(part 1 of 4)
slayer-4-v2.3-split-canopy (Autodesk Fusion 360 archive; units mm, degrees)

design "slayer-4-v2.3" references "20x20 Flight Controller", "M3 x 0.5mm Thread 6mm LONG SOCKET HEAD CAP SCREW", "runcam_phoenix_2", "CADDXFPV Ratel 2.1mm", "Slayer Hurricane 4040", "EACHINE CCW TYRO79-1607-2800KV", "M2 x 0.4mm Thread 5mm LONG SOCKET HEAD CAP SCREW"
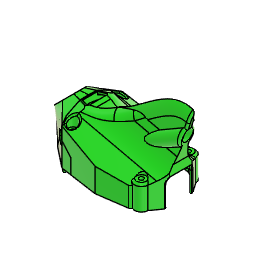
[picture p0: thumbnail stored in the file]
parameter "armstrength" = 5
parameter "d11" = 33
parameter "d12" = 48
parameter "d547" = 2
sketch "center-upper" plane through (0, 0, 0) normal (0, 0, 1) x axis (1, 0, 0)
  line L1 (-93, 0) -> (0, 0)
  line L2 (0, 100) -> (0, 0)
  line L3 (-24, 16.5) -> (-18.1019, 0)
  line L4 (0, 18.1019) -> (-24, 16.5)
  line L5 (0, 18.1019) -> (-10, 10)
  line L6 (-10, 10) -> (-18.1019, 0)
  line L7 (-25.4125, 15.9951) -> (-19.6949, 0)
  line L8 (-22.5875, 17.0049) -> (-16.509, 0)
  line L9 (-11.1655, 10.9443) -> (-20.0325, 0)
  line L10 (-8.8345, 9.0557) -> (-16.1714, 0)
  line L11 (-10.9443, 11.1655) -> (-0.9443, 19.2674)
  line L12 (-9.0557, 8.8345) -> (0.9443, 16.9364)
  line L13 (-35, 0) -> (0, 0)
  line L14 (-22.5875, 17.0049) -> (-24, 16.5)
  line L15 (-25.4125, 15.9951) -> (-24, 16.5)
  line L16 (-11.1655, 10.9443) -> (-10, 10)
  line L17 (-8.8345, 9.0557) -> (-10, 10)
  line L18 (-10.9443, 11.1655) -> (-10, 10)
  line L19 (-9.0557, 8.8345) -> (-10, 10)
  line L20 (-0.9443, 19.2674) -> (0, 18.1019)
  line L21 (0.9443, 16.9364) -> (0, 18.1019)
  line L22 (0.0999, 16.6053) -> (-23.9001, 15.0033)
  line L23 (-0.0999, 19.5986) -> (-24.0999, 17.9967)
  line L24 (-24.0999, 17.9967) -> (-24, 16.5)
  line L25 (-23.9001, 15.0033) -> (-24, 16.5)
  line L26 (-0.0999, 19.5986) -> (0, 18.1019)
  line L27 (0.0999, 16.6053) -> (0, 18.1019)
  line L28 (0, 30) -> (0, 0)
  line L29 (0, 1.5) -> (-18.1019, 1.5)
  line L30 (-18.1019, 1.5) -> (-18.1019, 0)
  line L31 (0, 0) -> (-10, 10)
  line L32 (-14.1459, 2.5) -> (0, 2.5)
  line L33 (-7.5042, 2.5) -> (-10, 10)
  circle C1 centre (-24, 16.5) radius 1.55
  circle C2 centre (0, 18.1019) radius 1.05
  circle C3 centre (-18.1019, 0) radius 1.05
  circle C4 centre (-10, 10) radius 1.05
  circle C5 centre (-24, 16.5) radius 5.5
  circle C6 centre (0, 18.1019) radius 3
  circle C7 centre (-10, 10) radius 3
  circle C8 centre (-18.1019, 0) radius 3
  point P3 (-24, 16.5)
  point P5 (-24, 16.5)
  point P1 (0, 0)
  point P6 (0, 0)
  point P4 (-18.1019, 0)
  point P8 (0, 0)
  point P2 (0, 18.1019)
  point P11 (-18.1019, 0)
  point P12 (-24, 16.5)
  point P13 (0, 18.1019)
  point P10 (-10, 10)
  point P14 (-10, 10)
  point P20 (-20.0325, 0)
  point P22 (-16.1714, 0)
  point P31 (0, 0)
  point P32 (-35, 0)
  point P33 (-24, 16.5)
  point P34 (-22.5875, 17.0049)
  point P19 (-24, 16.5)
  point P35 (-24, 16.5)
  point P36 (-25.4125, 15.9951)
  point P18 (-22.5875, 17.0049)
  point P16 (-25.4125, 15.9951)
  point P17 (-16.509, 0)
  point P15 (-19.6949, 0)
  point P29 (-10, 10)
  point P37 (-10, 10)
  point P38 (-11.1655, 10.9443)
  point P39 (-10, 10)
  point P40 (-8.8345, 9.0557)
  point P41 (-10, 10)
  point P42 (-10.9443, 11.1655)
  point P43 (-9.0557, 8.8345)
  point P25 (-10.9443, 11.1655)
  point P21 (-11.1655, 10.9443)
  point P23 (-8.8345, 9.0557)
  point P27 (-9.0557, 8.8345)
  point P44 (0, 18.1019)
  point P45 (-0.9443, 19.2674)
  point P46 (0.9443, 16.9364)
  point P24 (-0.9443, 19.2674)
  point P26 (0.9443, 16.9364)
  point P51 (-24.0999, 17.9967)
  point P52 (-24, 16.5)
  point P53 (-23.9001, 15.0033)
  point P49 (-24.0999, 17.9967)
  point P47 (-23.9001, 15.0033)
  point P28 (0, 18.1019)
  point P54 (0, 18.1019)
  point P55 (-0.0999, 19.5986)
  point P56 (0.0999, 16.6053)
  point P50 (-0.0999, 19.5986)
  point P48 (0.0999, 16.6053)
  point P57 (0, 30)
  point P60 (-18.1019, 0)
  point P61 (0, 2.5)
  point P62 (-14.1459, 2.5)
  point P63 (-7.5042, 2.5)
  coincident P3 P5
  coincident P1 P6
  coincident P4 L1
  coincident P1 P8
  coincident P2 L2
  coincident P4 P11
  coincident P3 P12
  coincident P2 P13
  coincident P10 P14
  parallel L3 L7
  parallel L3 L8
  concentric C1 C5
  coincident L1 P20
  parallel L6 L9
  coincident L1 P22
  parallel L6 L10
  parallel L5 L11
  parallel L5 L12
  concentric C2 C6
  concentric C4 C7
  concentric C3 C8
  coincident P1 P31
  coincident L1 P32
  perpendicular L2 L13
  coincident P3 P33
  coincident L8 P34
  perpendicular L8 L14
  coincident P19 P35
  coincident L7 P36
  perpendicular L7 L15
  coincident P18 P34
  coincident P16 P36
  coincident L1 P17
  coincident P15 L13
  coincident P29 P37
  coincident L9 P38
  perpendicular L9 L16
  coincident P10 P39
  coincident L10 P40
  perpendicular L10 L17
  coincident P29 P41
  coincident L11 P42
  perpendicular L11 L18
  coincident L12 P43
  perpendicular L12 L19
  coincident P25 L19
  coincident P21 P38
  coincident P23 P40
  coincident P27 P43
  coincident P2 P44
  coincident L11 P45
  perpendicular L11 L20
  coincident L12 P46
  perpendicular L12 L21
  coincident P24 P45
  coincident P26 P46
  parallel L4 L22
  parallel L4 L23
  coincident L23 P51
  perpendicular L23 L24
  coincident P3 P52
  coincident L22 P53
  perpendicular L22 L25
  coincident P49 P51
  coincident P47 P53
  coincident P28 P54
  coincident L23 P55
  perpendicular L23 L26
  coincident L22 P56
  perpendicular L22 L27
  coincident P50 P55
  coincident P48 P56
  coincident L2 P57
  horizontal L29
  coincident P4 P60
  perpendicular L29 L30
  coincident L28 P61
  coincident L10 P62
  perpendicular L28 L32
  coincident L32 P63
  dimension "d15" distance P2 P4 = 25.6
  dimension "d17" diameter C1 = 3.1
  dimension "d21" diameter C2 = 2.1
  dimension "d24" diameter C3 = 2.1 (= "d21")
  dimension "d27" distance P3 L1 = 16.5 (= "d11 / 2")
  dimension "d28" distance P3 L2 = 24 (= "d12 / 2")
  dimension "d34" diameter C4 = 2.1 (= "d21")
  dimension "d38" distance L2 P10 = 10
  dimension "d39" distance L1 P10 = 10
  dimension "d44" distance L3 L7 = 1.5
  dimension "d45" distance L3 L8 = 1.5 (= "d44")
  dimension "d47" distance L6 L9 = 1.5 (= "d44")
  dimension "d48" distance L6 L10 = 1.5 (= "d44")
  dimension "d49" distance L5 L11 = 1.5 (= "d44")
  dimension "d50" distance L5 L12 = 1.5 (= "d44")
  dimension "d51" diameter C5 = 11
  dimension "d52" diameter C8 = 6
  dimension "d53" diameter C7 = 6
  dimension "d54" diameter C6 = 6
  dimension "d55" distance L4 L23 = 1.5 (= "d44")
  dimension "d56" distance L4 L22 = 1.5 (= "d44")
  dimension "d93" distance L1 L29 = 1.5
  dimension "d118" distance L13 L32 = 2.5
extrude "Extrude2" new body sketch "center-upper" profile of C1 C2 C3 C4 L7 L8 C5 L9 L10 L11 L12 C6 C7 C8 L13 L22 L23 L28 along normal blind 2
fillet "Fillet6" radius 2
fillet "Fillet9" radius 5
fillet "Fillet7" radius 18
fillet "Fillet10" radius 20
fillet "Fillet147" radius 5
mirror "Mirror1" mirrorStitchTolerance 0.1
mirror "Mirror2" mirrorStitchTolerance 0.1
fillet "Fillet8" radius 9
sketch "center-upper-rear-cage" plane through (0, 0, 0) normal (0, 0, -1) x axis (1, 0, 0)
  line L1 (-10.419, 18.9098) -> (-7.8768, 19.0795)
  line L2 (-7.8768, -19.0795) -> (-10.419, -18.9098)
  line L3 (10.419, -18.9098) -> (7.8768, -19.0795)
  line L4 (7.8768, 19.0795) -> (10.419, 18.9098)
  line L5 (19.6919, -8.9044) -> (18.7852, -6.3678)
  line L6 (13.4936, -15.6979) -> (15.3167, -15.5763)
  line L7 (15.3479, -5.782) -> (13.4133, -8.1699)
  line L8 (18.7852, 6.3678) -> (19.6919, 8.9044)
  line L9 (13.4133, 8.1699) -> (15.3479, 5.782)
  line L10 (15.3167, 15.5763) -> (13.4936, 15.6979)
  line L11 (-19.6919, 8.9044) -> (-18.7852, 6.3678)
  line L12 (-13.4936, 15.6979) -> (-15.3167, 15.5763)
  line L13 (-15.3479, 5.782) -> (-13.4133, 8.1699)
  line L14 (-18.7852, -6.3678) -> (-19.6919, -8.9044)
  line L15 (-13.4133, -8.1699) -> (-15.3479, -5.782)
  line L16 (-15.3167, -15.5763) -> (-13.4936, -15.6979)
  line L17 (19, 3) -> (32.4985, 3)
  line L18 (31.3257, 6) -> (20, 6)
  line L19 (35.4985, 3.9489) -> (29.0384, 18.7057)
  line L20 (35.4985, 0) -> (35.4985, 3.9489)
  line L21 (28.2548, 13.0148) -> (31.3257, 6)
  line L22 (32.4985, 0) -> (32.4985, 3)
  line L23 (35.4985, 0) -> (32.4985, 0)
  line L24 (20, 6) -> (19, 3)
  line L25 (29.0384, 18.7057) -> (28.2548, 13.0148)
  line L26 (-22.1379, 6.8345) -> (-22.6368, 8.2301)
  line L27 (-22.6368, -8.2301) -> (-22.1379, -6.8345)
  line L28 (22.1379, -6.8345) -> (22.6368, -8.2301)
  line L29 (22.6368, 8.2301) -> (22.1379, 6.8345)
  circle C1 centre (0, 18.1019) radius 1.05
  arc A1 centre (0, 18.1019) radius 3 clockwise from (-1.2965, 20.8073) to (1.2965, 20.8073)
  arc A2 centre (-9.0756, 37.0396) radius 18 clockwise from (-1.2965, 20.8073) to (-7.8768, 19.0795)
  arc A3 centre (-11.751, 38.8654) radius 20 clockwise from (-10.419, 18.9098) to (-21.3581, 21.3239)
  arc A4 centre (-24, 16.5) radius 5.5 clockwise from (-25.7522, 11.2866) to (-21.3581, 21.3239)
  arc A5 centre (-24, -16.5) radius 5.5 clockwise from (-21.3581, -21.3239) to (-25.7522, -11.2866)
  arc A6 centre (-11.751, -38.8654) radius 20 clockwise from (-21.3581, -21.3239) to (-10.419, -18.9098)
  arc A7 centre (-9.0756, -37.0396) radius 18 clockwise from (-7.8768, -19.0795) to (-1.2965, -20.8073)
  arc A8 centre (0, -18.1019) radius 3 clockwise from (1.2965, -20.8073) to (-1.2965, -20.8073)
  arc A9 centre (9.0756, -37.0396) radius 18 clockwise from (1.2965, -20.8073) to (7.8768, -19.0795)
  arc A10 centre (11.751, -38.8654) radius 20 clockwise from (10.419, -18.9098) to (21.3581, -21.3239)
  arc A11 centre (24, -16.5) radius 5.5 clockwise from (25.7522, -11.2866) to (21.3581, -21.3239)
  arc A12 centre (24, 16.5) radius 5.5 clockwise from (21.3581, 21.3239) to (25.7522, 11.2866)
  arc A13 centre (11.751, 38.8654) radius 20 clockwise from (21.3581, 21.3239) to (10.419, 18.9098)
  arc A14 centre (9.0756, 37.0396) radius 18 clockwise from (7.8768, 19.0795) to (1.2965, 20.8073)
  arc A15 centre (10, 10) radius 3 clockwise from (8.3417, 7.5) to (7.5, 8.3417)
  arc A16 centre (3.3668, 0) radius 9 clockwise from (8.3417, 7.5) to (8.3417, -7.5)
  arc A17 centre (10, -10) radius 3 clockwise from (7.5, -8.3417) to (8.3417, -7.5)
  arc A18 centre (0, -3.3668) radius 9 clockwise from (7.5, -8.3417) to (-7.5, -8.3417)
  arc A19 centre (-10, -10) radius 3 clockwise from (-8.3417, -7.5) to (-7.5, -8.3417)
  arc A20 centre (-3.3668, 0) radius 9 clockwise from (-8.3417, -7.5) to (-8.3417, 7.5)
  arc A21 centre (-10, 10) radius 3 clockwise from (-7.5, 8.3417) to (-8.3417, 7.5)
  arc A22 centre (0, 3.3668) radius 9 clockwise from (-7.5, 8.3417) to (7.5, 8.3417)
  circle C2 centre (24, -16.5) radius 1.55
  circle C3 centre (10, -10) radius 1.05
  arc A23 centre (14.9837, -10.5874) radius 5 clockwise from (19.6919, -8.9044) to (15.3167, -15.5763)
  arc A24 centre (13.3604, -13.7024) radius 2 clockwise from (13.4936, -15.6979) to (12.0163, -12.2214)
  arc A25 centre (10, -10) radius 3 clockwise from (12.9804, -9.6573) to (12.0163, -12.2214)
  arc A26 centre (14.9673, -9.4289) radius 2 clockwise from (12.9804, -9.6573) to (13.4133, -8.1699)
  arc A27 centre (16.9019, -7.041) radius 2 clockwise from (15.3479, -5.782) to (18.7852, -6.3678)
  arc A28 centre (16.9019, 7.041) radius 2 clockwise from (18.7852, 6.3678) to (15.3479, 5.782)
  arc A29 centre (14.9673, 9.4289) radius 2 clockwise from (13.4133, 8.1699) to (12.9804, 9.6573)
  arc A30 centre (10, 10) radius 3 clockwise from (12.0163, 12.2214) to (12.9804, 9.6573)
  arc A31 centre (13.3604, 13.7024) radius 2 clockwise from (12.0163, 12.2214) to (13.4936, 15.6979)
  arc A32 centre (14.9837, 10.5874) radius 5 clockwise from (15.3167, 15.5763) to (19.6919, 8.9044)
  circle C4 centre (10, 10) radius 1.05
  circle C5 centre (24, 16.5) radius 1.55
  circle C6 centre (18.1019, 0) radius 1.05
  circle C7 centre (-18.1019, 0) radius 1.05
  circle C8 centre (-24, 16.5) radius 1.55
  circle C9 centre (-10, 10) radius 1.05
  arc A33 centre (-14.9837, 10.5874) radius 5 clockwise from (-19.6919, 8.9044) to (-15.3167, 15.5763)
  arc A34 centre (-13.3604, 13.7024) radius 2 clockwise from (-13.4936, 15.6979) to (-12.0163, 12.2214)
  arc A35 centre (-10, 10) radius 3 clockwise from (-12.9804, 9.6573) to (-12.0163, 12.2214)
  arc A36 centre (-14.9673, 9.4289) radius 2 clockwise from (-12.9804, 9.6573) to (-13.4133, 8.1699)
  arc A37 centre (-16.9019, 7.041) radius 2 clockwise from (-15.3479, 5.782) to (-18.7852, 6.3678)
  arc A38 centre (-16.9019, -7.041) radius 2 clockwise from (-18.7852, -6.3678) to (-15.3479, -5.782)
  arc A39 centre (-14.9673, -9.4289) radius 2 clockwise from (-13.4133, -8.1699) to (-12.9804, -9.6573)
  arc A40 centre (-10, -10) radius 3 clockwise from (-12.0163, -12.2214) to (-12.9804, -9.6573)
  arc A41 centre (-13.3604, -13.7024) radius 2 clockwise from (-12.0163, -12.2214) to (-13.4936, -15.6979)
  arc A42 centre (-14.9837, -10.5874) radius 5 clockwise from (-15.3167, -15.5763) to (-19.6919, -8.9044)
  circle C10 centre (-10, -10) radius 1.05
  circle C11 centre (-24, -16.5) radius 1.55
  circle C12 centre (0, -18.1019) radius 1.05
  arc A43 centre (-39.0876, 0.7757) radius 18 clockwise from (-22.1379, 6.8345) to (-21.0999, 0.1108)
  arc A44 centre (-18.1019, 0) radius 3 clockwise from (-21.0999, -0.1108) to (-21.0999, 0.1108)
  arc A45 centre (-39.0876, -0.7757) radius 18 clockwise from (-21.0999, -0.1108) to (-22.1379, -6.8345)
  arc A46 centre (39.0876, -0.7757) radius 18 clockwise from (22.1379, -6.8345) to (21.0999, -0.1108)
  arc A47 centre (18.1019, 0) radius 3 clockwise from (21.0999, 0.1108) to (21.0999, -0.1108)
  arc A48 centre (39.0876, 0.7757) radius 18 clockwise from (21.0999, 0.1108) to (22.1379, 6.8345)
  arc A49 centre (-27.345, 6.5471) radius 5 clockwise from (-25.7522, 11.2866) to (-22.6368, 8.2301)
  arc A50 centre (-27.345, -6.5471) radius 5 clockwise from (-22.6368, -8.2301) to (-25.7522, -11.2866)
  arc A51 centre (27.345, -6.5471) radius 5 clockwise from (25.7522, -11.2866) to (22.6368, -8.2301)
  arc A52 centre (27.345, 6.5471) radius 5 clockwise from (22.6368, 8.2301) to (25.7522, 11.2866)
  point P114 (29.0384, 18.7057)
  point P117 (28.2548, 13.0148)
  horizontal L17
  horizontal L18
  midpoint A12 P114
  tangent A12 L19
  vertical L20
  coincident A12 P117
  parallel L19 L21
  perpendicular L17 L22
  perpendicular L20 L23
  dimension "d83" distance L17 L18 = 3
  dimension "d84" distance L19 L21 = 3
  dimension "d85" distance L20 L22 = 3
  dimension "d88" distance L17 L23 = 3
extrude "Extrude3" new body sketch "center-upper-rear-cage" profile of A12 L17 L18 L19 L20 L21 L22 L23 against normal blind 2 bodies "center-upper"
mirror "Mirror3" mirrorStitchTolerance 0.1
combine "Combine1"
fillet "Fillet11" radius 2
extrude "Extrude4" new body sketch "center-upper" profile of C3 C4 L7 L8 L9 L10 L12 C7 C8 L13 L28 L29 L30 L32 L33 no distance stored bodies "puzzle"
sketch "puzzle" plane through (0, 0, -5) normal (0, 0, -1) x axis (1, 0, 0)
  line L1 (0, 0) -> (0, -2.5)
  line L2 (-17.0519, 0) -> (0, 0)
  line L3 (-21.1019, 0) -> (-19.1519, 0)
  line L4 (-12.801, -8.9256) -> (-17.6319, -2.9629)
  line L5 (-7.5042, -2.5) -> (-9.0528, -7.1535)
  line L6 (0, -2.5) -> (-7.5042, -2.5)
  line L7 (-21.1019, -13) -> (-10, -13)
  line L8 (-21.1019, 0) -> (-21.1019, -13)
  line L9 (-15.0963, -6.0926) -> (-24, -16.5)
  line L10 (-5.2336, -20.4063) -> (-29.0797, -0.0054)
  circle C1 centre (-10, -10) radius 1.05
  arc A1 centre (-18.1019, 0) radius 1.05 clockwise from (-17.0519, 0) to (-19.1519, 0)
  arc A2 centre (-18.1019, 0) radius 3 clockwise from (-17.6319, -2.9629) to (-21.1019, 0)
  arc A3 centre (-10, -10) radius 3 clockwise from (-9.0528, -7.1535) to (-12.801, -8.9256)
  arc A4 centre (-7.8796, 0) radius 13.2223 clockwise from (-10.6223, -12.9348) to (-21.1019, 0)
  point P14 (-10.6223, -12.9348)
  point P8 (-21.1019, 0)
  point P13 (-21.1019, 0)
  point P16 (-10, -13)
  tangent A2 A4
  coincident A3 P14
  coincident P8 P13
  tangent A3 A4
  coincident A3 P16
  tangent A3 L7
  parallel L3 L7
  tangent A2 L8
  perpendicular L9 L10
extrude "Extrude6" add sketch "puzzle" profile of A2 L4 A3 A4 L7 L8 L10 no distance stored
fillet "Fillet13" radius 2
sketch "arm" plane through (0, 0, 0) normal (0, 0, -1) x axis (1, 0, 0)
  line L1 (30.099, 8.8021) -> (29.2912, 10.6474)
  line L2 (-18.7852, -6.3678) -> (-19.6919, -8.9044)
  line L3 (-13.4133, -8.1699) -> (-15.3479, -5.782)
  line L4 (-15.3167, -15.5763) -> (-13.4936, -15.6979)
  line L5 (-19.6919, 8.9044) -> (-18.7852, 6.3678)
  line L6 (-13.4936, 15.6979) -> (-15.3167, 15.5763)
  line L7 (-15.3479, 5.782) -> (-13.4133, 8.1699)
  line L8 (18.7852, 6.3678) -> (19.6919, 8.9044)
  line L9 (13.4133, 8.1699) -> (15.3479, 5.782)
  line L10 (15.3167, 15.5763) -> (13.4936, 15.6979)
  line L11 (19.6919, -8.9044) -> (18.7852, -6.3678)
  line L12 (13.4936, -15.6979) -> (15.3167, -15.5763)
  line L13 (15.3479, -5.782) -> (13.4133, -8.1699)
  line L14 (29.0384, 18.7057) -> (35.3306, 4.3323)
  line L15 (7.8768, 19.0795) -> (10.419, 18.9098)
  line L16 (-10.419, 18.9098) -> (-7.8768, 19.0795)
  line L17 (-7.8768, -19.0795) -> (-10.419, -18.9098)
  line L18 (10.419, -18.9098) -> (7.8768, -19.0795)
  line L19 (-84.0942, 0) -> (0, 0)
  line L20 (-24, -16.5) -> (-62.0622, -60.9901)
  line L21 (-15.0963, -6.0926) -> (-24, -16.5)
  line L22 (-23.7088, -10.0065) -> (-69.0022, -62.949)
  line L23 (-24.2912, -22.9935) -> (-62.9232, -68.1496)
  line L24 (14.551, -2.5) -> (-14.551, -2.5)
  line L25 (14.551, -2.5) -> (-24.0545, -2.5)
  line L26 (-35, 0) -> (0, 0)
  line L27 (-12.0227, -2.5) -> (-15.0963, -6.0926)
  line L28 (-15.3457, -3) -> (-29.6478, -19.7174)
  line L29 (-9.1275, -2.5) -> (-26.3044, -22.5778)
  line L30 (-12.0023, -5.8604) -> (-15.3457, -3)
  line L31 (-62.9232, -68.1496) -> (-69.0022, -62.949)
  line L32 (-62.8385, -51.0203) -> (-62.0622, -60.9901)
  line L33 (-60.5096, -80.9298) -> (-62.0622, -60.9901)
  line L34 (-82.0019, -62.5427) -> (-62.0622, -60.9901)
  line L35 (-52.0924, -60.2138) -> (-62.0622, -60.9901)
  line L36 (-65.4439, -55.7133) -> (-67.7989, -58.4659)
  line L37 (-68.7344, -58.5364) -> (-74.9847, -60.0141)
  line L38 (-68.2741, -64.4471) -> (-74.6778, -63.9546)
  line L39 (-63.0382, -73.9126) -> (-64.5159, -67.6623)
  line L40 (-59.0977, -73.6057) -> (-58.6053, -67.202)
  line L41 (-35.7249, -16.6683) -> (-20.8845, -29.3646)
  line L42 (32.4985, -1) -> (32.4985, 1)
  line L43 (23.0892, -3) -> (30.4985, -3)
  line L44 (30.4985, 3) -> (23.0892, 3)
  line L45 (24.7203, 6) -> (28.2669, 6)
  line L46 (28.2669, -6) -> (24.7203, -6)
  line L47 (29.2912, -10.6474) -> (30.099, -8.8021)
  line L48 (35.3306, -4.3323) -> (29.0384, -18.7057)
  line L49 (-22.1379, 6.8345) -> (-22.6368, 8.2301)
  line L50 (-22.6368, -8.2301) -> (-22.1379, -6.8345)
  line L51 (35.4985, 3.5303) -> (35.4985, -3.5303)
  arc A1 centre (27.4591, 9.8453) radius 2 clockwise from (26.5366, 11.6199) to (29.2912, 10.6474)
  circle C1 centre (0, -18.1019) radius 1.05
  circle C2 centre (-24, -16.5) radius 1.55
  circle C3 centre (-10, -10) radius 1.05
  arc A2 centre (-16.9019, -7.041) radius 2 clockwise from (-18.7852, -6.3678) to (-15.3479, -5.782)
  arc A3 centre (-14.9673, -9.4289) radius 2 clockwise from (-13.4133, -8.1699) to (-12.9804, -9.6573)
  arc A4 centre (-10, -10) radius 3 clockwise from (-12.0163, -12.2214) to (-12.9804, -9.6573)
  arc A5 centre (-13.3604, -13.7024) radius 2 clockwise from (-12.0163, -12.2214) to (-13.4936, -15.6979)
  arc A6 centre (-14.9837, -10.5874) radius 5 clockwise from (-15.3167, -15.5763) to (-19.6919, -8.9044)
  arc A7 centre (-14.9837, 10.5874) radius 5 clockwise from (-19.6919, 8.9044) to (-15.3167, 15.5763)
  arc A8 centre (-13.3604, 13.7024) radius 2 clockwise from (-13.4936, 15.6979) to (-12.0163, 12.2214)
  arc A9 centre (-10, 10) radius 3 clockwise from (-12.9804, 9.6573) to (-12.0163, 12.2214)
  arc A10 centre (-14.9673, 9.4289) radius 2 clockwise from (-12.9804, 9.6573) to (-13.4133, 8.1699)
  arc A11 centre (-16.9019, 7.041) radius 2 clockwise from (-15.3479, 5.782) to (-18.7852, 6.3678)
  circle C4 centre (-10, 10) radius 1.05
  circle C5 centre (-24, 16.5) radius 1.55
  circle C6 centre (-18.1019, 0) radius 1.05
  circle C7 centre (18.1019, 0) radius 1.05
  circle C8 centre (24, 16.5) radius 1.55
  circle C9 centre (10, 10) radius 1.05
  arc A12 centre (16.9019, 7.041) radius 2 clockwise from (18.7852, 6.3678) to (15.3479, 5.782)
  arc A13 centre (14.9673, 9.4289) radius 2 clockwise from (13.4133, 8.1699) to (12.9804, 9.6573)
  arc A14 centre (10, 10) radius 3 clockwise from (12.0163, 12.2214) to (12.9804, 9.6573)
  arc A15 centre (13.3604, 13.7024) radius 2 clockwise from (12.0163, 12.2214) to (13.4936, 15.6979)
  arc A16 centre (14.9837, 10.5874) radius 5 clockwise from (15.3167, 15.5763) to (19.6919, 8.9044)
  arc A17 centre (14.9837, -10.5874) radius 5 clockwise from (19.6919, -8.9044) to (15.3167, -15.5763)
  arc A18 centre (13.3604, -13.7024) radius 2 clockwise from (13.4936, -15.6979) to (12.0163, -12.2214)
  arc A19 centre (10, -10) radius 3 clockwise from (12.9804, -9.6573) to (12.0163, -12.2214)
  arc A20 centre (14.9673, -9.4289) radius 2 clockwise from (12.9804, -9.6573) to (13.4133, -8.1699)
  arc A21 centre (16.9019, -7.041) radius 2 clockwise from (15.3479, -5.782) to (18.7852, -6.3678)
  circle C10 centre (10, -10) radius 1.05
  circle C11 centre (24, -16.5) radius 1.55
  arc A22 centre (10, 10) radius 3 clockwise from (8.3417, 7.5) to (7.5, 8.3417)
  arc A23 centre (3.3668, 0) radius 9 clockwise from (8.3417, 7.5) to (8.3417, -7.5)
  arc A24 centre (10, -10) radius 3 clockwise from (7.5, -8.3417) to (8.3417, -7.5)
  arc A25 centre (0, -3.3668) radius 9 clockwise from (7.5, -8.3417) to (-7.5, -8.3417)
  arc A26 centre (-10, -10) radius 3 clockwise from (-8.3417, -7.5) to (-7.5, -8.3417)
  arc A27 centre (-3.3668, 0) radius 9 clockwise from (-8.3417, -7.5) to (-8.3417, 7.5)
  arc A28 centre (-10, 10) radius 3 clockwise from (-7.5, 8.3417) to (-8.3417, 7.5)
  arc A29 centre (0, 3.3668) radius 9 clockwise from (-7.5, 8.3417) to (7.5, 8.3417)
  circle C12 centre (0, 18.1019) radius 1.05
  arc A30 centre (24, 16.5) radius 5.5 clockwise from (26.5366, 11.6199) to (25.7522, 11.2866)
  arc A31 centre (11.751, 38.8654) radius 20 clockwise from (21.3581, 21.3239) to (10.419, 18.9098)
  arc A32 centre (9.0756, 37.0396) radius 18 clockwise from (7.8768, 19.0795) to (1.2965, 20.8073)
  arc A33 centre (0, 18.1019) radius 3 clockwise from (-1.2965, 20.8073) to (1.2965, 20.8073)
  arc A34 centre (-9.0756, 37.0396) radius 18 clockwise from (-1.2965, 20.8073) to (-7.8768, 19.0795)
  arc A35 centre (-11.751, 38.8654) radius 20 clockwise from (-10.419, 18.9098) to (-21.3581, 21.3239)
  arc A36 centre (-24, 16.5) radius 5.5 clockwise from (-25.7522, 11.2866) to (-21.3581, 21.3239)
  arc A37 centre (-24, -16.5) radius 5.5 clockwise from (-21.3581, -21.3239) to (-25.7522, -11.2866)
  arc A38 centre (-11.751, -38.8654) radius 20 clockwise from (-21.3581, -21.3239) to (-10.419, -18.9098)
  arc A39 centre (-9.0756, -37.0396) radius 18 clockwise from (-7.8768, -19.0795) to (-1.2965, -20.8073)
  arc A40 centre (0, -18.1019) radius 3 clockwise from (1.2965, -20.8073) to (-1.2965, -20.8073)
  arc A41 centre (9.0756, -37.0396) radius 18 clockwise from (1.2965, -20.8073) to (7.8768, -19.0795)
  arc A42 centre (11.751, -38.8654) radius 20 clockwise from (10.419, -18.9098) to (21.3581, -21.3239)
  arc A43 centre (24, -16.5) radius 5.5 clockwise from (29.0384, -18.7057) to (21.3581, -21.3239)
  circle C13 centre (-24, -16.5) radius 1.55
  circle C14 centre (-62.0622, -60.9901) radius 50.8
  circle C15 centre (-24, -16.5) radius 6.5
  circle C16 centre (-62.0622, -60.9901) radius 2.5
  circle C17 centre (-62.528, -55.0082) radius 1.075
  circle C18 centre (-61.5964, -66.972) radius 1.075
  circle C19 centre (-68.0441, -61.4559) radius 1.075
  circle C20 centre (-62.528, -55.0082) radius 3
  circle C21 centre (-61.5964, -66.972) radius 3
  circle C22 centre (-68.0441, -61.4559) radius 3
  circle C23 centre (-74.5245, -61.9605) radius 2
  circle C24 centre (-61.0918, -73.4524) radius 2
  circle C25 centre (-62.0622, -60.9901) radius 6
  circle C26 centre (-62.0622, -60.9901) radius 57.15
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  point P115 (-62.0622, -60.9901)
  point P116 (-62.0622, -60.9901)
  point P114 (-24, -16.5)
  point P118 (-24, -16.5)
  point P130 (-12.0227, -2.5)
  point P131 (-9.1275, -2.5)
  point P132 (-12.0023, -5.8604)
  point P133 (-15.3457, -3)
  point P134 (-62.0622, -60.9901)
  point P135 (-62.0622, -60.9901)
  point P138 (-62.0622, -60.9901)
  point P141 (-62.528, -55.0082)
  point P142 (-61.5964, -66.972)
  point P143 (-68.0441, -61.4559)
  point P147 (-67.7989, -58.4659)
  point P148 (-65.4439, -55.7133)
  point P149 (-74.5245, -61.9605)
  point P150 (-74.9847, -60.0141)
  point P151 (-68.7344, -58.5364)
  point P152 (-74.6778, -63.9546)
  point P153 (-68.2741, -64.4471)
  point P154 (-61.0918, -73.4524)
  point P155 (-64.5159, -67.6623)
  point P156 (-63.0382, -73.9126)
  point P157 (-58.6053, -67.202)
  point P158 (-59.0977, -73.6057)
  point P128 (-29.6478, -19.7174)
  point P129 (-26.3044, -22.5778)
  point P161 (-23.7088, -10.0065)
  point P160 (-24.2912, -22.9935)
  point P66 (8.3417, 7.5)
  point P67 (8.3417, 7.5)
  point P71 (7.5, -8.3417)
  point P72 (7.5, -8.3417)
  point P64 (7.5, 8.3417)
  point P65 (7.5, 8.3417)
  point P68 (8.3417, -7.5)
  point P70 (8.3417, -7.5)
  point P73 (-7.5, -8.3417)
  point P75 (-7.5, -8.3417)
  point P76 (-8.3417, -7.5)
  point P77 (-8.3417, -7.5)
  point P78 (-8.3417, 7.5)
  point P80 (-8.3417, 7.5)
  point P81 (-7.5, 8.3417)
  point P82 (-7.5, 8.3417)
  point P136 (-62.8385, -51.0203)
  point P137 (-60.5096, -80.9298)
  point P139 (-82.0019, -62.5427)
  point P140 (-52.0924, -60.2138)
  point P146 (-68.0441, -61.4559)
  point P145 (-61.5964, -66.972)
  point P127 (-24, -16.5)
  horizontal L19
  coincident P115 P116
  coincident P114 P118
  parallel L20 L21
  parallel L20 L22
  parallel L20 L23
  parallel L24 L25
  concentric C13 C15
  parallel L21 L27
  coincident L25 P130
  parallel L21 L28
  coincident L25 P131
  parallel L21 L29
  coincident L29 P132
  perpendicular L22 L31
  coincident L30 P133
  perpendicular L28 L30
  coincident P116 P134
  coincident P134 P135
  coincident P115 P138
  coincident L32 P141
  coincident L33 P142
  coincident L34 P143
  perpendicular L32 L34
  perpendicular L33 L34
  perpendicular L33 L35
  concentric C17 C20
  concentric C18 C21
  concentric C19 C22
  coincident C22 P147
  coincident C20 P148
  parallel L23 L36
  coincident L34 P149
  coincident C23 P150
  coincident C22 P151
  tangent C22 L37
  coincident C23 P152
  coincident C22 P153
  tangent C22 L38
  tangent C23 L37
  tangent C23 L38
  coincident L33 P154
  coincident C21 P155
  coincident C24 P156
  tangent C24 L39
  coincident C21 P157
  coincident C24 P158
  tangent C24 L40
  tangent C21 L40
  tangent C21 L39
  concentric C14 C25
  tangent L36 C25
  coincident C15 P128
  coincident C15 P129
  coincident C15 P161
  coincident C15 P160
  concentric C14 C26
  perpendicular L22 L41
  coincident P66 P67
  coincident P71 P72
  coincident P64 P65
  coincident P68 P70
  coincident P73 P75
  coincident P76 P77
  coincident P78 P80
  coincident P81 P82
  dimension "d105" diameter C14 = 101.6
  dimension "d114" distance L20 L22 = 4
  dimension "d115" distance L21 L23 = 4 (= "d114")
  dimension "d117" distance L25 L26 = 2.5
  dimension "d121" diameter C15 = 13
  dimension "d155" diameter C16 = 5
  dimension "d156" distance P135 P136 = 10
  dimension "d157" distance P135 P137 = 20
  dimension "d158" distance P138 P139 = 20
  dimension "d159" distance P138 P140 = 10
  dimension "d160" diameter C17 = 2.15
  dimension "d162" diameter C19 = 2.15 (= "d160")
  dimension "d163" diameter C18 = 2.15 (= "d160")
  dimension "d164" distance P115 P141 = 6
  dimension "d165" distance P115 P143 = 6 (= "d164")
  dimension "d167" distance P115 P142 = 6 (= "d164")
  dimension "d168" angle L20 L32 = 45
  dimension "d169" diameter C20 = 6
  dimension "d170" diameter C22 = 6 (= "d169")
  dimension "d172" diameter C21 = 6 (= "d169")
  dimension "d173" distance P115 L31 = 6
  dimension "d175" distance P115 L36 = 6 (= "d173")
  dimension "d181" diameter C23 = 4
  dimension "d182" distance P146 P149 = 6.5
  dimension "d183" diameter C24 = 4 (= "d181")
  dimension "d184" distance P145 P154 = 6.5 (= "d182")
  dimension "d711" diameter C26 = 114.3
  dimension "d801" diameter = 152.4 (= "6")
  dimension "d802" diameter = 127 (= "5")
  dimension "d803" distance P127 L41 = 7.75
  dimension "d804" distance P115 L41 = 50.8 (= "d105 / 2")
extrude "Extrude5" new body sketch "arm" profile of C2 L2 A2 L3 A6 A37 A38 C13 L22 L23 C15 L28 L29 L30 L31 C16 C17 C18 C19 C20 C21 C22 L36 C23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 along normal blind 5 (= "armstrength") bodies "arm-fr"
fillet "Fillet18" radius 20
fillet "Fillet132" radius 4
fillet "Fillet19" radius 10
fillet "Fillet144" radius 18
chamfer "Chamfer17" distance 4 distance 2
chamfer "Chamfer18" distance 4 distance 2
fillet "Fillet145" radius 3
combine "Combine2"
sketch "puzzle-reduction" plane through (0, 0, -5) normal (0, 0, -1) x axis (1, 0, 0)
  line L1 (-16.3271, -10.9155) -> (-12.0023, -5.8604)
  line L2 (-7.9596, -3.8685) -> (-8.5531, -5.6519)
  line L3 (0, -2.5) -> (-6.0619, -2.5)
  line L4 (0, 0) -> (0, -2.5)
  line L5 (-17.0519, 0) -> (0, 0)
  line L6 (-21.1019, 0) -> (-19.1519, 0)
  line L7 (-15.3457, -3) -> (-19.6705, -8.0552)
  line L8 (-12.0023, -5.8604) -> (-15.3457, -3)
  line L9 (-13, -2.5) -> (0, -2.5)
  line L10 (-21.1019, -2.15) -> (-18.1019, -2.15)
  line L11 (-12.15, -13) -> (-12.15, -10)
  line L12 (-8.5531, -5.6519) -> (-11.4831, -8.4434)
  line L13 (-15.0133, -12.0395) -> (-16.3271, -10.9155)
  line L14 (-10, -13) -> (-12.413, -13)
  line L15 (-21.1019, -4.9885) -> (-21.1019, 0)
  line L16 (-19.6705, -8.0552) -> (-19.7023, -8.028)
  arc A1 centre (-10, -10) radius 3 clockwise from (-7.9932, -7.77) to (-10, -13)
  arc A2 centre (-6.6554, -6.2834) radius 2 clockwise from (-7.9932, -7.77) to (-8.5531, -5.6519)
  arc A3 centre (-6.0619, -4.5) radius 2 clockwise from (-7.9596, -3.8685) to (-6.0619, -2.5)
  arc A4 centre (-18.1019, 0) radius 1.05 clockwise from (-17.0519, 0) to (-19.1519, 0)
  circle C1 centre (-10, -10) radius 1.05
  circle C2 centre (-10, -10) radius 2.9998
  circle C3 centre (-18.1019, 0) radius 3
  circle C4 centre (-18.1019, 0) radius 2.15
  circle C5 centre (-10, -10) radius 2.15
  arc A5 centre (-12.413, -9) radius 4 clockwise from (-12.413, -13) to (-15.0133, -12.0395)
  arc A6 centre (-17.1019, -4.9885) radius 4 clockwise from (-19.7023, -8.028) to (-21.1019, -4.9885)
  point P12 (0, -2.5)
  point P21 (0, -2.5)
  point P17 (-21.1019, 0)
  point P26 (-18.1019, -2.15)
  point P28 (-12.15, -10)
  point P30 (-11.4831, -8.4434)
  point P29 (-12.15, -13)
  point P7 (-8.5531, -5.6519)
  point P37 (-8.5531, -5.6519)
  point P27 (-21.1019, -2.15)
  concentric A1 C2
  coincident P12 P21
  perpendicular L4 L9
  concentric A4 C3
  coincident P17 C3
  concentric A4 C4
  concentric C2 C5
  coincident C4 P26
  tangent C4 L10
  horizontal L10
  coincident C5 P28
  tangent C5 L11
  vertical L11
  coincident C5 P30
  tangent C5 L12
  coincident P29 L14
  coincident P7 P37
  coincident P27 L15
  dimension "d151" diameter C4 = 4.3
  dimension "d152" diameter C5 = 4.3
extrude "Extrude7" cut sketch "puzzle-reduction" profile of A1 A2 L5 A4 L6 C1 C2 C3 C4 C5 L10 L11 L12 L14 L15 against normal blind 2
fillet "Fillet15" radius 2
fillet "Fillet16" radius 2
mirror "Mirror6" mirrorStitchTolerance 0.1
mirror "Mirror7" mirrorStitchTolerance 0.1
sketch "puzzle reduction-2" plane through (0, 0, 0) normal (0, 0, 1) x axis (-1, 0, 0)
  line L1 (16.6459, 4.5197) -> (19.6705, 8.0552)
  line L2 (13.522, 4.5602) -> (13.826, 4.3002)
  line L3 (16.3271, 10.9155) -> (13.3025, 7.3801)
  line L4 (7.9596, 3.8685) -> (8.5531, 5.6519)
  line L5 (0, 2.5) -> (6.0619, 2.5)
  line L6 (-8.5531, 5.6519) -> (-7.9596, 3.8685)
  line L7 (-13.3025, 7.3801) -> (-16.3271, 10.9155)
  line L8 (-13.826, 4.3002) -> (-13.522, 4.5602)
  line L9 (-19.6705, 8.0552) -> (-16.6459, 4.5197)
  line L10 (-16.6459, -4.5197) -> (-19.6705, -8.0552)
  line L11 (-13.522, -4.5602) -> (-13.826, -4.3002)
  line L12 (-16.3271, -10.9155) -> (-13.3025, -7.3801)
  line L13 (-7.9596, -3.8685) -> (-8.5531, -5.6519)
  line L14 (6.0619, -2.5) -> (0, -2.5)
  line L15 (8.5531, -5.6519) -> (7.9596, -3.8685)
  line L16 (13.3025, -7.3801) -> (16.3271, -10.9155)
  line L17 (13.826, -4.3002) -> (13.522, -4.5602)
  line L18 (19.6705, -8.0552) -> (16.6459, -4.5197)
  line L19 (-11.3, 0) -> (11.3, 0)
  line L20 (8.3152, -4.9371) -> (12.5467, -1.5639)
  line L21 (8.3152, 4.9371) -> (12.5467, 1.5639)
  line L22 (0, -20) -> (0, -2.5)
  line L23 (-8.3152, -4.9371) -> (-12.5467, -1.5639)
  line L24 (-8.3152, 4.9371) -> (-12.5467, 1.5639)
  line L25 (-6.0619, 2.5) -> (0, 2.5)
  line L26 (0, -2.5) -> (-6.0619, -2.5)
  line L27 (21.1019, 4.9885) -> (21.1019, -4.9885)
  line L28 (19.6705, 8.0552) -> (19.7023, 8.028)
  line L29 (15.0133, 12.0395) -> (16.3271, 10.9155)
  line L30 (10, 13) -> (12.413, 13)
  line L31 (-12.413, 13) -> (-10, 13)
  line L32 (-16.3271, 10.9155) -> (-15.0133, 12.0395)
  line L33 (-19.7023, 8.028) -> (-19.6705, 8.0552)
  line L34 (-21.1019, -4.9885) -> (-21.1019, 4.9885)
  line L35 (-19.6705, -8.0552) -> (-19.7023, -8.028)
  line L36 (-15.0133, -12.0395) -> (-16.3271, -10.9155)
  line L37 (-10, -13) -> (-12.413, -13)
  line L38 (12.413, -13) -> (10, -13)
  line L39 (16.3271, -10.9155) -> (15.0133, -12.0395)
  line L40 (19.7023, -8.028) -> (19.6705, -8.0552)
  circle C1 centre (-10, -10) radius 1.05
  circle C2 centre (-10, 10) radius 1.05
  circle C3 centre (-18.1019, 0) radius 1.05
  circle C4 centre (18.1019, 0) radius 1.05
  circle C5 centre (10, 10) radius 1.05
  arc A1 centre (15.1262, 5.8199) radius 2 clockwise from (16.6459, 4.5197) to (13.826, 4.3002)
  arc A2 centre (14.8222, 6.0799) radius 2 clockwise from (13.522, 4.5602) to (13.3025, 7.3801)
  arc A3 centre (10, 10) radius 3 clockwise from (7.9932, 7.77) to (10, 13)
  arc A4 centre (6.6554, 6.2834) radius 2 clockwise from (7.9932, 7.77) to (8.5531, 5.6519)
  arc A5 centre (6.0619, 4.5) radius 2 clockwise from (7.9596, 3.8685) to (6.0619, 2.5)
  arc A6 centre (-6.0619, 4.5) radius 2 clockwise from (-6.0619, 2.5) to (-7.9596, 3.8685)
  arc A7 centre (-6.6554, 6.2834) radius 2 clockwise from (-8.5531, 5.6519) to (-7.9932, 7.77)
  arc A8 centre (-10, 10) radius 3 clockwise from (-10, 13) to (-7.9932, 7.77)
  arc A9 centre (-14.8222, 6.0799) radius 2 clockwise from (-13.3025, 7.3801) to (-13.522, 4.5602)
  arc A10 centre (-15.1262, 5.8199) radius 2 clockwise from (-13.826, 4.3002) to (-16.6459, 4.5197)
  arc A11 centre (-15.1262, -5.8199) radius 2 clockwise from (-16.6459, -4.5197) to (-13.826, -4.3002)
  arc A12 centre (-14.8222, -6.0799) radius 2 clockwise from (-13.522, -4.5602) to (-13.3025, -7.3801)
  arc A13 centre (-10, -10) radius 3 clockwise from (-7.9932, -7.77) to (-10, -13)
  arc A14 centre (-6.6554, -6.2834) radius 2 clockwise from (-7.9932, -7.77) to (-8.5531, -5.6519)
  arc A15 centre (-6.0619, -4.5) radius 2 clockwise from (-7.9596, -3.8685) to (-6.0619, -2.5)
  arc A16 centre (6.0619, -4.5) radius 2 clockwise from (6.0619, -2.5) to (7.9596, -3.8685)
  arc A17 centre (6.6554, -6.2834) radius 2 clockwise from (8.5531, -5.6519) to (7.9932, -7.77)
  arc A18 centre (10, -10) radius 3 clockwise from (10, -13) to (7.9932, -7.77)
  arc A19 centre (14.8222, -6.0799) radius 2 clockwise from (13.3025, -7.3801) to (13.522, -4.5602)
  arc A20 centre (15.1262, -5.8199) radius 2 clockwise from (13.826, -4.3002) to (16.6459, -4.5197)
  circle C6 centre (10, -10) radius 1.05
  circle C7 centre (11.3, 0) radius 2
  circle C8 centre (-11.3, 0) radius 2
  arc A21 centre (17.1019, 4.9885) radius 4 clockwise from (19.7023, 8.028) to (21.1019, 4.9885)
  arc A22 centre (12.413, 9) radius 4 clockwise from (12.413, 13) to (15.0133, 12.0395)
  arc A23 centre (-12.413, 9) radius 4 clockwise from (-15.0133, 12.0395) to (-12.413, 13)
  arc A24 centre (-17.1019, 4.9885) radius 4 clockwise from (-21.1019, 4.9885) to (-19.7023, 8.028)
  arc A25 centre (-17.1019, -4.9885) radius 4 clockwise from (-19.7023, -8.028) to (-21.1019, -4.9885)
  arc A26 centre (-12.413, -9) radius 4 clockwise from (-12.413, -13) to (-15.0133, -12.0395)
  arc A27 centre (12.413, -9) radius 4 clockwise from (15.0133, -12.0395) to (12.413, -13)
  arc A28 centre (17.1019, -4.9885) radius 4 clockwise from (21.1019, -4.9885) to (19.7023, -8.028)
  point P68 (11.3, 0)
  point P70 (11.3, 0)
  point P69 (-11.3, 0)
  point P71 (-11.3, 0)
  point P72 (12.5467, -1.5639)
  point P73 (8.3152, -4.9371)
  point P74 (12.5467, 1.5639)
  point P75 (8.3152, 4.9371)
  point P78 (-12.5467, -1.5639)
  point P79 (-8.3152, -4.9371)
  point P80 (-12.5467, 1.5639)
  point P81 (-8.3152, 4.9371)
  point P1 (0, 0)
  coincident P68 P70
  coincident P69 P71
  horizontal L19
  coincident C7 P72
  coincident L15 P73
  tangent C7 L20
  symmetric L19 P72 P74
  symmetric L19 P73 P75
  symmetric P72 L22 P78
  symmetric P73 L22 P79
  symmetric P74 L22 P80
  symmetric P75 L22 P81
  dimension "d145" diameter C7 = 4
  dimension "d146" distance P1 P68 = 11.3
  dimension "d147" distance P1 P69 = 11.3 (= "d146")
  dimension "d148" diameter C8 = 4 (= "d145")
extrude "Extrude8" cut sketch "puzzle reduction-2" profile of C7 C8 against normal blind 4
fillet "Fillet17" radius 2.1
mirror "Mirror8" mirrorStitchTolerance 0.1 bodies "arm-fl"
mirror "Mirror9" mirrorStitchTolerance 0.1 bodies "arm-rl", "arm-rr"
sketch "center-lower" plane through (0, 0, -5) normal (0, 0, -1) x axis (1, 0, 0)
  line L1 (-16.6459, -4.5197) -> (-19.6705, -8.0552)
  line L2 (-13.522, -4.5602) -> (-13.826, -4.3002)
  line L3 (-16.3271, -10.9155) -> (-13.3025, -7.3801)
  line L4 (-8.9138, -5.9956) -> (-11.4831, -8.4434)
  line L5 (0, -2.5) -> (-6.0619, -2.5)
  line L6 (11.4831, -8.4434) -> (8.9138, -5.9956)
  line L7 (13.3025, -7.3801) -> (16.3271, -10.9155)
  line L8 (13.826, -4.3002) -> (13.522, -4.5602)
  line L9 (19.6705, -8.0552) -> (16.6459, -4.5197)
  line L10 (18.1019, -2.15) -> (19.1019, -2.15)
  line L11 (19.1019, 2.15) -> (18.1019, 2.15)
  line L12 (16.6459, 4.5197) -> (19.6705, 8.0552)
  line L13 (13.522, 4.5602) -> (13.826, 4.3002)
  line L14 (16.3271, 10.9155) -> (13.3025, 7.3801)
  line L15 (8.9138, 5.9956) -> (11.4831, 8.4434)
  line L16 (0, 2.5) -> (6.0619, 2.5)
  line L17 (-11.4831, 8.4434) -> (-8.9138, 5.9956)
  line L18 (-13.3025, 7.3801) -> (-16.3271, 10.9155)
  line L19 (-13.826, 4.3002) -> (-13.522, 4.5602)
  line L20 (-19.6705, 8.0552) -> (-16.6459, 4.5197)
  line L21 (-18.1019, 2.15) -> (-19.1019, 2.15)
  line L22 (-19.1019, -2.15) -> (-18.1019, -2.15)
  line L23 (-40.0019, -6) -> (-40.0019, 6)
  line L24 (-61.9019, 0) -> (-18.1019, 0)
  line L25 (-26.0782, 18.8035) -> (-40.0019, 6)
  line L26 (-58.9176, 6) -> (-40.0019, 6)
  line L27 (-24, 0) -> (-24, 16.5)
  line L28 (-10.0302, 13.8124) -> (-24, 16.5)
  line L29 (-25.5, 16.5) -> (-25.5, 0)
  line L30 (-25.5, 16.5) -> (-24, 16.5)
  line L31 (-22.5, 16.5) -> (-22.5, 0)
  line L32 (-24, 16.5) -> (-22.5, 16.5)
  line L33 (-10.0302, 15.8491) -> (-23.6222, 18.464)
  line L34 (-18.8229, 13.4673) -> (-24.3778, 14.536)
  line L35 (-24, 16.5) -> (-23.6222, 18.464)
  line L36 (-24, 16.5) -> (-24.3778, 14.536)
  line L37 (0, 21.814) -> (0, 0)
  line L38 (-10.0302, 11.7757) -> (-18.8229, 13.4673)
  line L39 (-22.5, 0) -> (-25.5, 0)
  line L40 (18.1019, 0) -> (-18.1019, 0)
  curve K1 (-15, 0) -> (-27.0933, 11.3589)
  curve K2 (-25.8767, 10.6539) -> (-28.31, 12.0638)
  curve K3 (-15, -1.2506) -> (-15, 1.2506)
  curve K4 (-9.2694, 0) -> (-19.8418, 20.8254)
  curve K5 (-9.2694, -2) -> (-9.2694, 2)
  line L41 (-9.2694, 0) -> (-15, 0)
  curve K6 (-18.8808, 19.9254) -> (-20.8028, 21.7254)
  line L42 (-7.9596, -3.8685) -> (-8.3957, -5.1791)
  line L43 (8.3957, -5.1791) -> (7.9596, -3.8685)
  line L44 (7.9596, 3.8685) -> (8.3957, 5.1791)
  line L45 (-8.3957, 5.1791) -> (-7.9596, 3.8685)
  line L46 (-9.9272, 4) -> (0, 4)
  line L47 (0, 0) -> (0, 4)
  line L48 (0, 0) -> (-9.2694, 0)
  line L49 (-25.5, 3) -> (-37.0019, 3)
  line L50 (-25.5, 6) -> (-35.5698, 6)
  line L51 (-37.0019, 3) -> (-37.0019, 0)
  line L52 (-28.4852, 12.5146) -> (-35.5698, 6)
  line L53 (-37.0019, 0) -> (-40.0019, 0)
  line L54 (0, 15.8491) -> (-10.0302, 15.8491)
  line L55 (0, 11.7757) -> (-10.0302, 11.7757)
  line L56 (0, 11.7757) -> (0, 15.8491)
  line L57 (6.0619, -2.5) -> (0, -2.5)
  line L58 (-6.0619, 2.5) -> (0, 2.5)
  line L59 (-21.1019, -4.9885) -> (-21.1019, -4.15)
  line L60 (-19.6705, -8.0552) -> (-19.7023, -8.028)
  line L61 (-15.4502, -11.6658) -> (-16.3271, -10.9155)
  line L62 (-12.15, -10) -> (-12.15, -10.146)
  line L63 (12.15, -10.146) -> (12.15, -10)
  line L64 (16.3271, -10.9155) -> (15.4502, -11.6658)
  line L65 (19.7023, -8.028) -> (19.6705, -8.0552)
  line L66 (21.1019, -4.15) -> (21.1019, -4.9885)
  line L67 (21.1019, 4.9885) -> (21.1019, 4.15)
  line L68 (19.6705, 8.0552) -> (19.7023, 8.028)
  line L69 (15.4502, 11.6658) -> (16.3271, 10.9155)
  line L70 (12.15, 10) -> (12.15, 10.146)
  line L71 (-12.15, 10.146) -> (-12.15, 10)
  line L72 (-16.3271, 10.9155) -> (-15.4502, 11.6658)
  line L73 (-19.7023, 8.028) -> (-19.6705, 8.0552)
  line L74 (-21.1019, 4.15) -> (-21.1019, 4.9885)
  arc A1 centre (-15.1262, -5.8199) radius 2 clockwise from (-16.6459, -4.5197) to (-13.826, -4.3002)
  arc A2 centre (-14.8222, -6.0799) radius 2 clockwise from (-13.522, -4.5602) to (-13.3025, -7.3801)
  arc A3 centre (-10, -10) radius 2.15 clockwise from (-12.15, -10) to (-11.4831, -8.4434)
  arc A4 centre (10, -10) radius 2.15 clockwise from (11.4831, -8.4434) to (12.15, -10)
  arc A5 centre (14.8222, -6.0799) radius 2 clockwise from (13.3025, -7.3801) to (13.522, -4.5602)
  arc A6 centre (15.1262, -5.8199) radius 2 clockwise from (13.826, -4.3002) to (16.6459, -4.5197)
  arc A7 centre (18.1019, 0) radius 2.15 clockwise from (18.1019, -2.15) to (18.1019, 2.15)
  arc A8 centre (15.1262, 5.8199) radius 2 clockwise from (16.6459, 4.5197) to (13.826, 4.3002)
  arc A9 centre (14.8222, 6.0799) radius 2 clockwise from (13.522, 4.5602) to (13.3025, 7.3801)
  arc A10 centre (10, 10) radius 2.15 clockwise from (12.15, 10) to (11.4831, 8.4434)
  arc A11 centre (-10, 10) radius 2.15 clockwise from (-11.4831, 8.4434) to (-12.15, 10)
  arc A12 centre (-14.8222, 6.0799) radius 2 clockwise from (-13.3025, 7.3801) to (-13.522, 4.5602)
  arc A13 centre (-15.1262, 5.8199) radius 2 clockwise from (-13.826, 4.3002) to (-16.6459, 4.5197)
  arc A14 centre (-18.1019, 0) radius 2.15 clockwise from (-18.1019, 2.15) to (-18.1019, -2.15)
  circle C1 centre (-24, 16.5) radius 1.55
  circle C2 centre (-18.1019, 0) radius 1.05
  circle C3 centre (-10, 10) radius 1.05
  circle C4 centre (0, 18.1019) radius 1.05
  circle C5 centre (10, 10) radius 1.05
  circle C6 centre (18.1019, 0) radius 1.05
  circle C7 centre (-24, 16.5) radius 6
  arc A15 centre (-10.2934, -4.5476) radius 2 clockwise from (-8.3957, -5.1791) to (-8.9138, -5.9956)
  arc A16 centre (-6.0619, -4.5) radius 2 clockwise from (-7.9596, -3.8685) to (-6.0619, -2.5)
  arc A17 centre (6.0619, -4.5) radius 2 clockwise from (6.0619, -2.5) to (7.9596, -3.8685)
  arc A18 centre (10.2934, -4.5476) radius 2 clockwise from (8.9138, -5.9956) to (8.3957, -5.1791)
  arc A19 centre (10.2934, 4.5476) radius 2 clockwise from (8.3957, 5.1791) to (8.9138, 5.9956)
  arc A20 centre (6.0619, 4.5) radius 2 clockwise from (7.9596, 3.8685) to (6.0619, 2.5)
  arc A21 centre (-6.0619, 4.5) radius 2 clockwise from (-6.0619, 2.5) to (-7.9596, 3.8685)
  arc A22 centre (-10.2934, 4.5476) radius 2 clockwise from (-8.9138, 5.9956) to (-8.3957, 5.1791)
  arc A23 centre (-19.1019, -4.15) radius 2 clockwise from (-21.1019, -4.15) to (-19.1019, -2.15)
  arc A24 centre (-17.1019, -4.9885) radius 4 clockwise from (-19.7023, -8.028) to (-21.1019, -4.9885)
  arc A25 centre (-14.15, -10.146) radius 2 clockwise from (-12.15, -10.146) to (-15.4502, -11.6658)
  arc A26 centre (14.15, -10.146) radius 2 clockwise from (15.4502, -11.6658) to (12.15, -10.146)
  arc A27 centre (17.1019, -4.9885) radius 4 clockwise from (21.1019, -4.9885) to (19.7023, -8.028)
  arc A28 centre (19.1019, -4.15) radius 2 clockwise from (19.1019, -2.15) to (21.1019, -4.15)
  arc A29 centre (19.1019, 4.15) radius 2 clockwise from (21.1019, 4.15) to (19.1019, 2.15)
  arc A30 centre (17.1019, 4.9885) radius 4 clockwise from (19.7023, 8.028) to (21.1019, 4.9885)
  arc A31 centre (14.15, 10.146) radius 2 clockwise from (12.15, 10.146) to (15.4502, 11.6658)
  arc A32 centre (-14.15, 10.146) radius 2 clockwise from (-15.4502, 11.6658) to (-12.15, 10.146)
  arc A33 centre (-17.1019, 4.9885) radius 4 clockwise from (-21.1019, 4.9885) to (-19.7023, 8.028)
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  point P65 (-18.1019, 0)
  point P72 (-18.1019, 0)
  point P64 (-24, 16.5)
  point P77 (-24, 16.5)
  point P78 (-24, 0)
  point P76 (-24, 16.5)
  point P79 (-24, 16.5)
  point P81 (-25.5, 0)
  point P83 (-24, 16.5)
  point P84 (-22.5, 0)
  point P1 (0, 0)
  point P88 (0, 0)
  point P90 (-18.8229, 13.4673)
  point P32 (18.1019, 0)
  point P91 (18.1019, 0)
  point P92 (-27.0933, 11.3589)
  point P93 (-15, 0)
  point P98 (-19.8418, 20.8254)
  point P99 (-9.2694, 0)
  point P120 (0, 4)
  point P121 (-9.9272, 4)
  point P122 (0, 0)
  point P123 (0, 0)
  point P125 (-25.5, 3)
  point P127 (-25.5, 6)
  point P128 (-37.0019, 0)
  point P129 (-28.4852, 12.5146)
  point P130 (-40.0019, 0)
  point P131 (-10.0302, 15.8491)
  point P132 (-10.0302, 11.7757)
  point P80 (-10.0302, 13.8124)
  point P70 (-40.0019, 6)
  point P71 (-40.0019, -6)
  vertical L23
  coincident P65 P72
  horizontal L24
  midpoint L23 L24
  horizontal L26
  concentric C1 C7
  coincident P64 P77
  coincident L24 P78
  perpendicular L24 L27
  coincident P76 P79
  coincident L24 P81
  perpendicular L24 L29
  coincident P76 P83
  perpendicular L27 L30
  coincident L24 P84
  perpendicular L27 L32
  parallel L27 L31
  perpendicular L28 L35
  perpendicular L28 L36
  parallel L28 L34
  parallel L28 L33
  coincident P1 P88
  vertical L37
  coincident C7 P90
  parallel L28 L38
  coincident P32 P91
  coincident C7 P92
  coincident L40 P93
  midpoint P92 K2
  midpoint P93 K3
  parallel L37 K3
  coincident C7 P98
  coincident L40 P99
  midpoint P99 K5
  parallel L37 K5
  midpoint P98 K6
  coincident L37 P120
  coincident K4 P121
  perpendicular L37 L46
  coincident P1 P122
  coincident P1 P123
  coincident L29 P125
  perpendicular L29 L49
  coincident L29 P127
  perpendicular L29 L50
  coincident L24 P128
  perpendicular L24 L51
  coincident C7 P129
  parallel L25 L52
  midpoint L23 P130
  vertical P131 P132
  vertical P80 P131
  parallel L37 L56
  parallel L40 L55
  parallel L54 L55
  dimension "d189" distance P65 L23 = 21.9
  dimension "d190" distance P70 P71 = 12
  dimension "d191" angle L25 L26 = 137.4
  dimension "d192" distance L27 L29 = 1.5
  dimension "d193" diameter C7 = 12
  dimension "d194" distance L27 L31 = 1.5 (= "d192")
  dimension "d195" distance L28 L33 = 2
  dimension "d196" distance L28 L34 = 2
  dimension "d224" distance L40 L46 = 4
  dimension "d228" distance L24 L49 = 3
  dimension "d229" distance L49 L50 = 3
  dimension "d230" distance L23 L51 = 3
  dimension "d231" distance L25 L52 = 3
extrude "Extrude9" new body sketch "center-lower" profile of L18 A12 L19 A13 L20 C1 C7 L29 L31 L33 L34 L38 L39 K1 K4 L41 A21 L45 L46 L47 L48 L54 L55 L56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 along normal blind 2
fillet "Fillet20" radius 14
fillet "Fillet146" radius 14
fillet "Fillet21" radius 2
mirror "Mirror11" mirrorStitchTolerance 0.1
sketch "center-lower-holes" plane through (0, 0, -7) normal (0, 0, -1) x axis (1, 0, 0)
  line L1 (-10.0302, 15.8491) -> (10.0302, 15.8491)
  line L2 (-11.8125, 16.192) -> (-10.0302, 15.8491)
  line L3 (-22.5, 0) -> (-25.5, 0)
  line L4 (-22.5, 4.5203) -> (-22.5, 0)
  curve K1 (-22.5, 4.5203) -> (-19.2416, 6.0748)
  curve K2 (-15, 0) -> (-19.2416, 6.0748)
  line L5 (15, 0) -> (-15, 0)
  curve K3 (15, 0) -> (19.2416, 6.0748)
  curve K4 (22.5, 4.5203) -> (19.2416, 6.0748)
  line L6 (22.5, 0) -> (22.5, 4.5203)
  line L7 (25.5, 0) -> (22.5, 0)
  line L8 (10.0302, 15.8491) -> (11.8125, 16.192)
  line L9 (9.9931, 11.7757) -> (-9.9931, 11.7757)
  curve K5 (11.9135, 8.8933) -> (10.0564, 11.7767)
  curve K6 (19.8418, 20.8254) -> (19.3632, 20.3456)
  line L10 (-9.9272, 4) -> (9.9272, 4)
  curve K7 (-19.8418, 20.8254) -> (-19.3632, 20.3456)
  curve K8 (-11.9135, 8.8933) -> (-10.0564, 11.7767)
  line L11 (0.3181, 11.7757) -> (-3.7825, 4)
  line L12 (-0.3909, 4) -> (3.7097, 11.7757)
  curve K9 (-11.8125, 16.192) -> (-19.3632, 20.3456)
  curve K10 (11.8125, 16.192) -> (19.3632, 20.3456)
  line L13 (25.5, 3.8608) -> (25.5, 0)
  curve K11 (10.0564, 11.7767) -> (9.9931, 11.7757)
  curve K12 (11.9135, 8.8933) -> (9.9272, 4)
  curve K13 (-11.9135, 8.8933) -> (-9.9272, 4)
  curve K14 (-10.0564, 11.7767) -> (-9.9931, 11.7757)
  line L14 (-25.5, 0) -> (-25.5, 3.8608)
  arc A1 centre (-24, 16.5) radius 6 clockwise from (-28.65, 12.7082) to (-19.8418, 20.8254)
  arc A2 centre (24, 16.5) radius 6 clockwise from (19.8418, 20.8254) to (28.65, 12.7082)
  circle C1 centre (24, 16.5) radius 1.55
  circle C2 centre (-24, 16.5) radius 1.55
  arc A3 centre (-39.5, 3.8608) radius 14 clockwise from (-28.65, 12.7082) to (-25.5, 3.8608)
  arc A4 centre (39.5, 3.8608) radius 14 clockwise from (25.5, 3.8608) to (28.65, 12.7082)
  point P35 (-0.3909, 4)
  point P32 (-3.7825, 4)
  point P34 (3.7097, 11.7757)
  point P33 (0.3181, 11.7757)
  coincident L10 P35
  parallel L11 L12
  coincident L10 P32
  coincident L9 P34
  coincident L9 P33
  dimension "d252" distance L11 L12 = 3
extrude "Extrude12" add sketch "center-lower-holes" profile of L9 L10 L11 L12 against normal blind 2
fillet "Fillet31" radius 2
mirror "Mirror12" mirrorStitchTolerance 0.1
